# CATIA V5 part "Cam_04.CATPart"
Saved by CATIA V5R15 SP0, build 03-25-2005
Part number: Cam_04
Material "Grey Blue": density 7860 kg/m3, Young's modulus 2e+11 Pa, Poisson ratio 0.266
Bounding box of the stored display mesh (mm): x -14 to 14, y -77.496 to 77.496, z -155.8 to 77.49
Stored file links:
  E:\#01 CATIA Lecture Materials\#06 DMU\#11 DMU Page01 KIN EX11\Cam_04.CATPart
  E:\V5_education\CATIA Data\KIN\Under Motor\Shaft_2.CATPart
  E:\V5_education\CATIA Data\KIN\Under Motor\Cam_04.CATPart
  C:\Program Files\Dassault Systemes\B20\win_b64\startup\materials\Catalog.CATMaterial
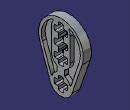
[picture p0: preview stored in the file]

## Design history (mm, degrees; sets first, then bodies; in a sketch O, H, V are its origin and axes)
Body1 (main body), material "Grey Blue"
  Sketch1 on yz-plane, origin (0, 0, 0), H (0, 1, 0), V (0, 0, 1)
    arc A1 centre (0, 0) radius 77.5 from (73.3238, -25.0972) to (-73.3238, -25.0972) ccw
    point P1 (0, -115.8)
    line L1 (-73.3238, -25.0972) -> (-37.8446, -128.7534)
    line L2 (73.3238, -25.0972) -> (37.8446, -128.7534)
    arc A2 centre (0, -115.8) radius 40 from (-37.8446, -128.7534) to (37.8446, -128.7534) ccw
    arc A3 centre (0, 0) radius 23.8 from (21.9289, -9.25) to (21.9289, 9.25) ccw
    construction line L3 through (0, 0) direction (1, 0)
    line L4 (-21.9289, 9.25) -> (-9.25, 9.25)
    line L5 (21.9289, -9.25) -> (9.25, -9.25)
    construction line L6 through (0, 0) direction (0, 1)
    line L7 (9.25, 21.9289) -> (9.25, 9.25)
    line L8 (-9.25, -21.9289) -> (-9.25, -9.25)
    point P6 (-9.25, -21.9289)
    point P7 (-21.9289, 9.25)
    arc A4 centre (0, 0) radius 23.8 from (-21.9289, 9.25) to (-21.9289, -9.25) ccw
    point P8 (9.25, 21.9289)
    point P9 (-9.25, 9.25)
    line L9 (9.25, 9.25) -> (21.9289, 9.25)
    line L10 (9.25, -9.25) -> (9.25, -21.9289)
    point P10 (-9.25, -9.25)
    line L11 (-9.25, 9.25) -> (-9.25, 21.9289)
    line L12 (-9.25, -9.25) -> (-21.9289, -9.25)
    point P11 (0, 0)
    arc A5 centre (0, -40) radius 23.8 from (21.9289, -49.25) to (21.9289, -30.75) ccw
    construction line L13 through (-1.2574, -40) direction (1, 0)
    line L14 (-21.9289, -30.75) -> (-9.25, -30.75)
    line L15 (21.9289, -49.25) -> (9.25, -49.25)
    construction line L16 through (0, -2.9117) direction (0, 1)
    line L17 (-9.25, -61.9289) -> (-9.25, -49.25)
    point P23 (-9.25, -61.9289)
    arc A6 centre (0, -40) radius 23.8 from (-9.25, -61.9289) to (9.25, -61.9289) ccw
    point P24 (-21.9289, -30.75)
    arc A7 centre (0, -40) radius 23.8 from (-21.9289, -30.75) to (-21.9289, -49.25) ccw
    point P25 (-9.25, -30.75)
    line L18 (9.25, -30.75) -> (21.9289, -30.75)
    line L19 (9.25, -49.25) -> (9.25, -61.9289)
    point P26 (-9.25, -49.25)
    line L20 (-9.25, -49.25) -> (-21.9289, -49.25)
    point P27 (0, -40)
    arc A8 centre (0, 40) radius 23.8 from (21.9289, 30.75) to (21.9289, 49.25) ccw
    construction line L21 through (-2.8862, 40) direction (1, 0)
    line L22 (-21.9289, 49.25) -> (-9.25, 49.25)
    line L23 (21.9289, 30.75) -> (9.25, 30.75)
    construction line L24 through (0, 0) direction (0, 1)
    line L25 (9.25, 61.9289) -> (9.25, 49.25)
    point P38 (-21.9289, 49.25)
    arc A9 centre (0, 40) radius 23.8 from (-21.9289, 49.25) to (-21.9289, 30.75) ccw
    point P39 (9.25, 61.9289)
    arc A10 centre (0, 40) radius 23.8 from (9.25, 61.9289) to (-9.25, 61.9289) ccw
    line L26 (9.25, 49.25) -> (21.9289, 49.25)
    point P41 (-9.25, 30.75)
    line L27 (-9.25, 49.25) -> (-9.25, 61.9289)
    line L28 (-9.25, 30.75) -> (-21.9289, 30.75)
    point P42 (0, 40)
    arc A11 centre (0, -119) radius 23.8 from (21.9289, -128.25) to (21.9289, -109.75) ccw
    construction line L29 through (5.2338, -119) direction (1, 0)
    line L30 (-21.9289, -109.75) -> (-9.25, -109.75)
    line L31 (21.9289, -128.25) -> (9.25, -128.25)
    construction line L32 through (0, 0) direction (0, 1)
    line L33 (9.25, -97.0711) -> (9.25, -109.75)
    line L34 (-9.25, -140.9289) -> (-9.25, -128.25)
    point P53 (-9.25, -140.9289)
    arc A12 centre (0, -119) radius 23.8 from (-9.25, -140.9289) to (9.25, -140.9289) ccw
    point P54 (-21.9289, -109.75)
    arc A13 centre (0, -119) radius 23.8 from (-21.9289, -109.75) to (-21.9289, -128.25) ccw
    point P55 (9.25, -97.0711)
    arc A14 centre (0, -119) radius 23.8 from (9.25, -97.0711) to (-9.25, -97.0711) ccw
    point P56 (-9.25, -109.75)
    line L35 (9.25, -109.75) -> (21.9289, -109.75)
    line L36 (9.25, -128.25) -> (9.25, -140.9289)
    point P57 (-9.25, -128.25)
    line L37 (-9.25, -109.75) -> (-9.25, -97.0711)
    line L38 (-9.25, -128.25) -> (-21.9289, -128.25)
    point P58 (0, -119)
    line L39 (9.25, -21.9289) -> (9.25, -30.75)
    line L40 (-9.25, -21.9289) -> (-9.25, -30.75)
    line L41 (9.25, 21.9289) -> (9.25, 30.75)
    line L42 (-9.25, 21.9289) -> (-9.25, 30.75)
    radius A1 = 77.5
    distance A2 A1 = 233.3
    radius A2 = 40
    radius A3 = 23.8
    distance L4 L5 = 18.5
    distance L3 L4 = 9.25
    distance L7 L8 = 18.5
    distance L6 L7 = 9.25
    radius A5 = 23.8
    distance L14 L15 = 18.5
    distance L13 L14 = 9.25
    distance L13 L3 = 40
    radius A8 = 23.8
    distance L22 L23 = 18.5
    distance L21 L22 = 9.25
    distance L24 L25 = 9.25
    distance L21 L3 = 40
    radius A11 = 23.8
    distance L30 L31 = 18.5
    distance L29 L30 = 9.25
    distance L33 L34 = 18.5
    distance L32 L33 = 9.25
    distance L29 L3 = 119
    distance L27 L25 = 18.5
    coincidence: P1 V, A3 P6, A3 P7, A3 A4, A3 P8, L8 P9, L4 L9, L7 L10, L5 P10, L8 L11, L5 L12, L6 V, P11 O, A5 P23, A5 A6, A5 P24, A5 A7, L17 P25, L14 L18, L15 P26, L15 L20, P27 L16, L16 L6, P27 L13, A8 P38, A8 A9, A8 P39, A8 A10, L22 L26, L23 P41, L23 L28, P42 L24, P42 L21, L24 L16, A11 P53, A11 A12, A11 P54, A11 A13, A11 P55, A11 A14, L34 P56, L30 L35, L33 L36, L31 P57, L34 L37, L31 L38, P58 L32, P58 L29, L32 L24, L19 L39
    tangency: L1 A1, L2 A1, L1 A2, A2 L2
    horizontal: L4 L3, L5 L3, L9 L3, L12 L3, L14 L13, L15 L13, L18 L13, L20 L13, L22 L21, L23 L21, L26 L21, L28 L21, L30 L29, L31 L29, L35 L29, L38 L29
    vertical: L7 L6, L8 L6, L10 L6, L11 L6, L17 L16, L19 L16, L25 L24, L27 L24, L33 L32, L34 L32, L36 L32, L37 L32, L39 V, L40 V, L41 V, L42 V
    symmetry: L5 L9 H
  Pad1: profile Sketch1, direction (1, 0, 0), length 14, mirrored extent
  Sketch2 on end face of Pad1, origin (14, 0, 0), H (0, 1, 0), V (0, 0, 1)
    arc A1 centre (0, 40) radius 32.5 from (32.5, 40) to (27.2813, 57.663) ccw
    point P1 (0, 40)
    arc A2 centre (0, -119) radius 32.5 from (30.5975, -108.0435) to (13.6594, -89.5098) ccw
    point P2 (0, -119)
    arc A3 centre (0, -40) radius 32.5 from (-32.5, -40) to (-13.6594, -69.4902) ccw
    point P3 (0, -40)
    reference projected arc E1 centre (0, -119) radius 23.8 from (9.25, -97.0711) to (-9.25, -97.0711) ccw from edge [end face of Pad1 | face of Pad1 from Sketch1.A14]
    reference projected arc E2 centre (0, -40) radius 23.8 from (-9.25, -61.9289) to (9.25, -61.9289) ccw from edge [end face of Pad1 | face of Pad1 from Sketch1.A6]
    line L1 (32.5, 40) -> (32.5, -40)
    line L2 (-32.5, 40) -> (-32.5, -40)
    reference projected arc E3 centre (0, 40) radius 23.8 from (9.25, 61.9289) to (-9.25, 61.9289) ccw from edge [end face of Pad1 | face of Pad1 from Sketch1.A10]
    offset line E4 (28.3834, -125.515) -> (63.8627, -21.8588) from edge [face of Pad1 from Sketch1.L2 | end face of Pad1]
    offset line E5 (34.3726, -108.0169) -> (63.8627, -21.8588) from edge [face of Pad1 from Sketch1.L2 | end face of Pad1]
    point P9 (63.8627, -21.8588)
    offset arc E6 centre (0, 0) radius 67.5 from (63.8627, -21.8588) to (-63.8627, -21.8588) ccw from edge [face of Pad1 from Sketch1.A1 | end face of Pad1]
    offset arc E7 centre (0, 0) radius 67.5 from (63.8627, -21.8588) to (29.8444, 60.5439) ccw from edge [face of Pad1 from Sketch1.A1 | end face of Pad1]
    offset arc E8 centre (0, 0) radius 67.5 from (-29.8444, 60.5439) to (-63.8627, -21.8588) ccw from edge [face of Pad1 from Sketch1.A1 | end face of Pad1]
    point P10 (63.8627, -21.8588)
    point P11 (-63.8627, -21.8588)
    offset line E9 (-63.8627, -21.8588) -> (-28.3834, -125.515) from edge [face of Pad1 from Sketch1.L1 | end face of Pad1]
    offset line E10 (-63.8627, -21.8588) -> (-34.3726, -108.0169) from edge [face of Pad1 from Sketch1.L1 | end face of Pad1]
    point P12 (-63.8627, -21.8588)
    arc A4 centre (0, 40) radius 32.5 from (-27.2813, 57.663) to (-32.5, 40) ccw
    arc A5 centre (32.4804, -107.3693) radius 2 from (30.5975, -108.0435) to (34.3726, -108.0169) ccw
    arc A6 centre (-32.4804, -107.3693) radius 2 from (-30.5975, -108.0435) to (-34.3726, -108.0169) cw
    arc A7 centre (28.9601, 58.75) radius 2 from (29.8444, 60.5439) to (27.2813, 57.663) ccw
    arc A8 centre (-28.9601, 58.75) radius 2 from (-27.2813, 57.663) to (-29.8444, 60.5439) ccw
    line L3 (-12.5, -71.305) -> (-12.5, -87.695)
    line L4 (12.5, -71.305) -> (12.5, -87.695)
    arc A9 centre (0, -40) radius 32.5 from (13.6594, -69.4902) to (32.5, -40) ccw
    arc A10 centre (0, -119) radius 32.5 from (-13.6594, -89.5098) to (-30.5975, -108.0435) ccw
    arc A11 centre (14.5, -71.305) radius 2 from (13.6594, -69.4902) to (12.5, -71.305) ccw
    arc A12 centre (-14.5, -71.305) radius 2 from (-13.6594, -69.4902) to (-12.5, -71.305) cw
    arc A13 centre (-14.5, -87.695) radius 2 from (-13.6594, -89.5098) to (-12.5, -87.695) ccw
    arc A14 centre (14.5, -87.695) radius 2 from (13.6594, -89.5098) to (12.5, -87.695) cw
    radius A2 = 32.5
    radius A3 = 32.5
    radius A1 = 32.5
    radius A5 = 2
    radius A6 = 2
    radius A7 = 2
    radius A8 = 2
    distance L4 L3 = 25
    radius A11 = 2
    radius A12 = 2
    radius A13 = 2
    radius A14 = 2
    coincidence: P1 V, P2 V, P3 V, A1 A4, A3 A9, A2 A10, P9 P10, P11 P12
    concentricity: A2 E1, A3 E2, P1 E3
    tangency: L1 A3, L2 A3, L2 A1, L1 A1, E6 E4, E9 E6, A5 E4, A5 A2, A6 A2, A6 E9, A7 E6, A7 A1, A8 A4, A8 E6, A11 A9, A11 L4, A12 L3, A12 A3, A13 L3, A13 A10, A14 L4, A14 A2
    vertical: L3 V, L4 V
    symmetry: L3 L4 V
  Pocket1: profile Sketch2, direction (-1, 0, 0), length 13
  Mirror1: of Pocket1, about yz-plane
  Fillet1: radius 3, on edge [face of Pad1 from Sketch1.L28 | face of Pad1 from Sketch1.L42]; edge [face of Pad1 from Sketch1.L41 | face of Pad1 from Sketch1.L23]; edge [face of Pad1 from Sketch1.L12 | face of Pad1 from Sketch1.L8]; edge [face of Pad1 from Sketch1.L10 | face of Pad1 from Sketch1.L5]; edge [face of Pad1 from Sketch1.L20 | face of Pad1 from Sketch1.L17]; edge [face of Pad1 from Sketch1.L19 | face of Pad1 from Sketch1.L15]; edge [face of Pad1 from Sketch1.L18 | face of Pad1 from Sketch1.L39]; edge [face of Pad1 from Sketch1.L40 | face of Pad1 from Sketch1.L14]; edge [face of Pad1 from Sketch1.L9 | face of Pad1 from Sketch1.L7]; edge [face of Pad1 from Sketch1.L11 | face of Pad1 from Sketch1.L4]; edge [face of Pad1 from Sketch1.L26 | face of Pad1 from Sketch1.L25]; edge [face of Pad1 from Sketch1.L27 | face of Pad1 from Sketch1.L22]; edge [face of Pad1 from Sketch1.L37 | face of Pad1 from Sketch1.L30]; edge [face of Pad1 from Sketch1.L35 | face of Pad1 from Sketch1.L33]; edge [face of Pad1 from Sketch1.L38 | face of Pad1 from Sketch1.L34]; edge [face of Pad1 from Sketch1.L36 | face of Pad1 from Sketch1.L31]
